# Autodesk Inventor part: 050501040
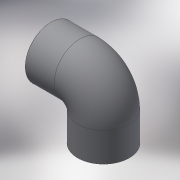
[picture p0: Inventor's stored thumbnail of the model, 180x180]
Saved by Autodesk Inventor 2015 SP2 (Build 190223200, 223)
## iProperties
Created: 2017-10
Part Number: 050501040
Material: Generic
Description: PLASSON THREADED 90° ELBOW PVC 4"
Document SubType Name: Modeling
Designer: KIM
Density: 1 g/cm^3
Appearance: Default
Author: KIM
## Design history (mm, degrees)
derived "050501.ipt"
feature "Solid1::050501.ipt"
tag "TaggingFeature1"
body "Solid1"
other parameters: "d7" = 1.10072, "d9" = 132, "d13" = 90 deg, "d19" = 90 deg, "d20" = 110.072, "d22" = 0, "d24" = 90 deg, "d26" = 99.0648, "d27" = 90 deg, "G_" = 110.072, "E_" = 132, "H_" = 186
